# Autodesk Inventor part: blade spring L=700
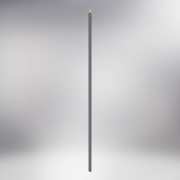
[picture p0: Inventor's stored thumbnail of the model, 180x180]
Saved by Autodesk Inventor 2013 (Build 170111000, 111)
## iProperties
Shininess: 25.0
Length Units: 11269
Angle Units: 11279
Time Units: 11290
Mass Units: 11283
Length Display Precision: 3
Angle Display Precision: 2
Created: 2002-03
Part Number: blade spring L=700
Material: Steel, Mild
Document SubType Name: Modeling
Designer: =<Author>
Density: 7.86 g/cm^3
Description: =<Part Number>
Density: 7.859999999999999
Volumn: 9.74725157027476
Area: 75.28846882187165
PropertySet Name: Model Information
Control State: 0
Master: False
Checked Out: True
Checked Out Date: 2008-10-15
Last Check In Date: 2008-10-15
Author: LAlexey
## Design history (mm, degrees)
sketch "Sketch1"
  geometry: L1 (-26.034, 11.829)-(-18.634, 11.829); L2 (-18.634, 11.829)-(-18.634, 8.029); L3 (-18.634, 8.029)-(-26.034, 8.029); L4 (-26.034, 8.029)-(-26.034, 11.829)
  constraints: 8 end point, 2 parallel, 1 horizontal, 1 perpendicular
  dimensions: "d0" = 3.8 distance between parallel lines of L3 L1; "d1" = 7.4 distance of L1.start L1.end
extrude "Extrusion1" new body sketch "Sketch1" distance "d2" = 550; taper "d3" = 0 deg
fillet "Fillet1" dims "d4" = 1
sketch "Sketch2"
  geometry: L1 (-18.634, 10.829)-(-18.634, 9.029) reference; L2 (-25.034, 11.829)-(-19.634, 11.829) reference; C1 r 1.5 at (-22.334, 9.929)
  constraints: 1 centre point
  dimensions: "d5" = 3 diameter of C1; "d6" = 1.9 distance from line of L2 C1.centre; "d7" = 3.7 distance from line of L1 C1.centre
extrude "Extrusion2" join sketch "Sketch2" distance "d8" = 5; taper "d9" = 0 deg
sketch "Sketch3"
  geometry: L1 (-5.4, 0)-(0, 0) reference; C1 r 2 at (-2.7, 542); 1 further point
  constraints: 1 centre point
  dimensions: "d10" = 4 diameter of C1; "d11" = 3.7 horizontal distance of point (1, 550) C1.centre; "d12" = 542 distance from line of L1 C1.centre
extrude "Extrusion3" cut sketch "Sketch3" distance "d13" = 5; taper "d14" = 0 deg
node "РабПлоскость1"
body "Solid1"
other parameters: "d15" = -3.7
